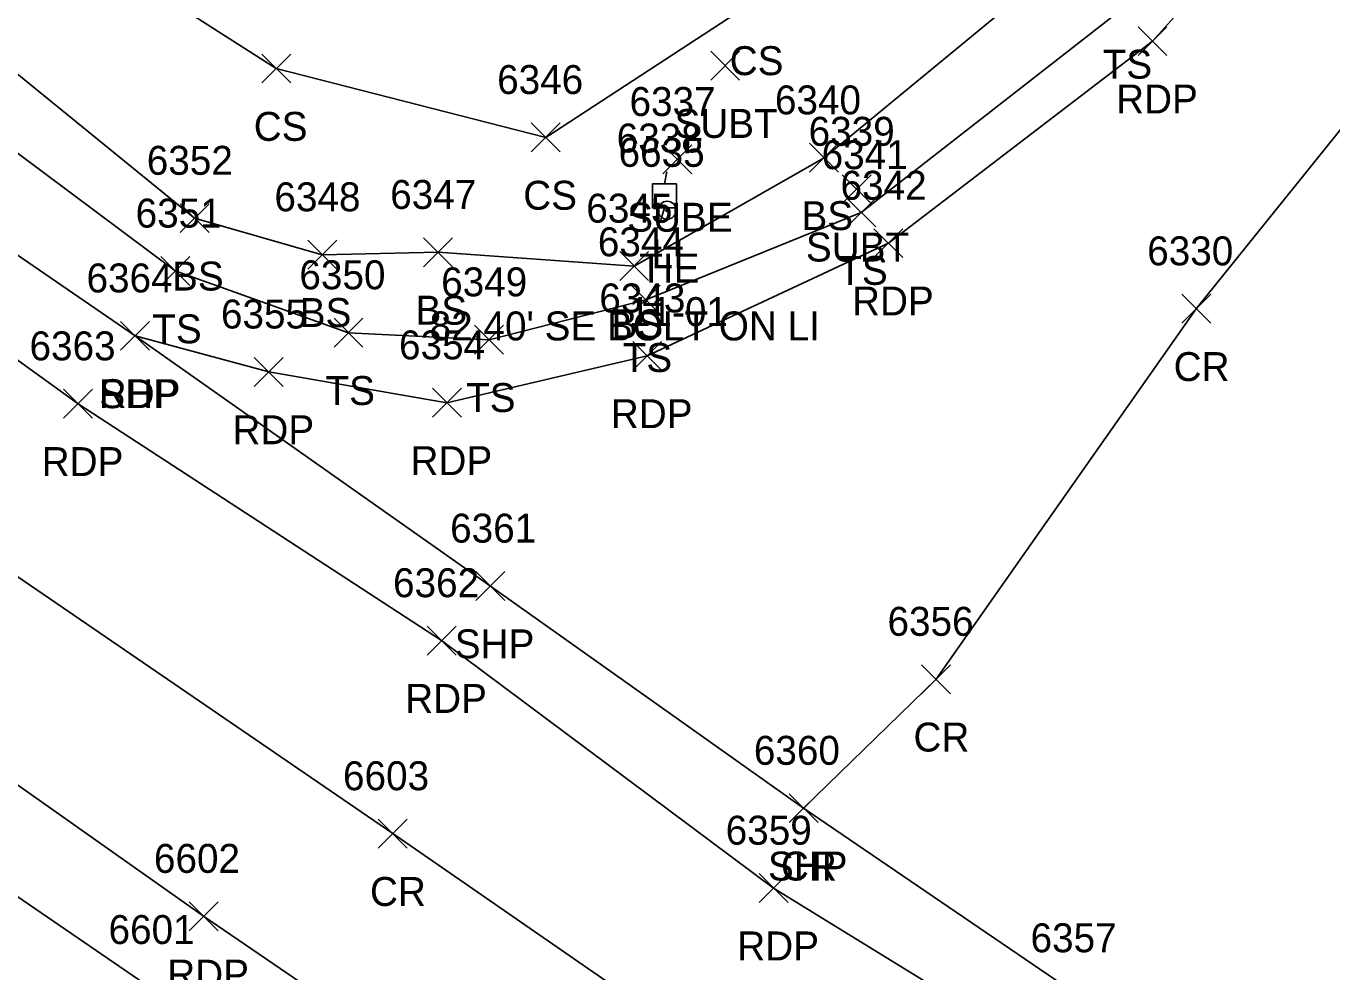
# Model space of a CAD drawing. Extents: x 1505656 to 1508446, y 700805 to 703031.
# Drawn here: x 1507831.5 to 1507921.8, y 701178.2 to 701243.5 of the extents above; entities that cross this region are included whole.
import ezdxf

# ---------------------------------------------------------------- set-up
doc = ezdxf.new("R2010")
doc.units = 0
for name, color, linetype in [('C_A', 7, 'Continuous'), ('C_C', 7, 'Continuous'), ('C_I', 7, 'Continuous'), ('CBP', 7, 'Continuous'), ('L_A', 7, 'Continuous'), ('L_I', 7, 'Continuous'), ('L_TIC', 7, 'Continuous'), ('LELB', 7, 'Continuous'), ('P_A', 7, 'Continuous'), ('P_I', 7, 'Continuous'), ('P_TIC', 7, 'Continuous'), ('PET', 7, 'Continuous'), ('PRC', 7, 'Continuous'), ('PSP', 7, 'Continuous'), ('U_A', 7, 'Continuous'), ('U_C', 7, 'Continuous'), ('U_I', 7, 'Continuous'), ('U_TIC', 7, 'Continuous'), ('ULP', 7, 'Continuous')]:
    doc.layers.add(name, color=color, linetype=linetype)

msp = doc.modelspace()

# ---------------------------------------------------------------- linework, layer by layer
at = {"layer": 'CBP'}
for radius in [0.625, 0.0833]:
    msp.add_circle((1507875.831, 701230.817), radius, dxfattribs=at)
at = {"layer": 'L_TIC'}
for points in [[(1507847.824, 701239.613), (1507849.824, 701241.613)], [(1507849.824, 701239.613), (1507847.824, 701241.613)], [(1507866.449, 701234.851), (1507868.449, 701236.851)], [(1507868.449, 701234.851), (1507866.449, 701236.851)], [(1507885.679, 701233.442), (1507887.679, 701235.442)], [(1507887.679, 701233.442), (1507885.679, 701235.442)], [(1507842.178, 701229.266), (1507844.178, 701231.266)], [(1507844.178, 701229.266), (1507842.178, 701231.266)], [(1507888.255, 701229.657), (1507890.255, 701231.657)], [(1507890.255, 701229.657), (1507888.255, 701231.657)], [(1507851, 701226.743), (1507853, 701228.743)], [(1507853, 701226.743), (1507851, 701228.743)], [(1507859.004, 701226.906), (1507861.004, 701228.906)], [(1507861.004, 701226.906), (1507859.004, 701228.906)], [(1507840.841, 701225.616), (1507842.841, 701227.616)], [(1507842.841, 701225.616), (1507840.841, 701227.616)], [(1507872.557, 701225.957), (1507874.557, 701227.957)], [(1507874.557, 701225.957), (1507872.557, 701227.957)], [(1507873.353, 701223.633), (1507875.353, 701225.633)], [(1507875.353, 701223.633), (1507873.353, 701225.633)], [(1507852.813, 701221.352), (1507854.813, 701223.352)], [(1507854.813, 701221.352), (1507852.813, 701223.352)], [(1507862.532, 701220.863), (1507864.532, 701222.863)], [(1507864.532, 701220.863), (1507862.532, 701222.863)]]:
    msp.add_lwpolyline(points, dxfattribs=at)
at = {"layer": 'LELB'}
for points in [[(1508013.247, 701346.104), (1507984.495, 701324.829), (1507956.473, 701302.426), (1507918.756, 701270.827), (1507904.064, 701248.775), (1507886.679, 701234.442), (1507873.557, 701226.957), (1507860.004, 701227.906), (1507852, 701227.743), (1507843.178, 701230.266), (1507815.133, 701253.103), (1507771.903, 701280.143), (1507738.232, 701303.159), (1507696.593, 701329.666), (1507663.203, 701353.106), (1507646.455, 701366.454)], [(1508015.052, 701343.612), (1507986.327, 701322.014), (1507960.585, 701298.459), (1507925.277, 701262.854), (1507907.529, 701244.915), (1507889.255, 701230.657), (1507874.353, 701224.633), (1507863.532, 701221.863), (1507853.813, 701222.352), (1507841.841, 701226.616), (1507812.686, 701248.413), (1507769.981, 701276.582), (1507735.611, 701299.665), (1507693.172, 701327.017), (1507661.005, 701349.446), (1507641.822, 701365.101)], [(1507916.993, 701276.137), (1507899.543, 701258.765), (1507881.721, 701245.155), (1507867.449, 701235.851), (1507848.824, 701240.613), (1507819.444, 701259.37), (1507776.79, 701286.758), (1507743.58, 701313.789), (1507698.164, 701337.222), (1507663.203, 701353.106)]]:
    msp.add_lwpolyline(points, dxfattribs=at)
at = {"layer": 'P_TIC'}
for points in [[(1507908.38, 701241.504), (1507910.38, 701243.504)], [(1507910.38, 701241.504), (1507908.38, 701243.504)], [(1507890.129, 701227.541), (1507892.129, 701229.541)], [(1507892.129, 701227.541), (1507890.129, 701229.541)], [(1507911.409, 701223.006), (1507913.409, 701225.006)], [(1507913.409, 701223.006), (1507911.409, 701225.006)], [(1507838.062, 701221.133), (1507840.062, 701223.133)], [(1507840.062, 701221.133), (1507838.062, 701223.133)], [(1507838.062, 701221.133), (1507840.062, 701223.133)], [(1507840.062, 701221.133), (1507838.062, 701223.133)], [(1507873.456, 701219.751), (1507875.456, 701221.751)], [(1507875.456, 701219.751), (1507873.456, 701221.751)], [(1507847.305, 701218.64), (1507849.305, 701220.64)], [(1507849.305, 701218.64), (1507847.305, 701220.64)], [(1507834.121, 701216.44), (1507836.121, 701218.44)], [(1507836.121, 701216.44), (1507834.121, 701218.44)], [(1507859.612, 701216.505), (1507861.612, 701218.505)], [(1507861.612, 701216.505), (1507859.612, 701218.505)], [(1507862.625, 701203.839), (1507864.625, 701205.839)], [(1507864.625, 701203.839), (1507862.625, 701205.839)], [(1507859.245, 701200.065), (1507861.245, 701202.065)], [(1507861.245, 701200.065), (1507859.245, 701202.065)], [(1507893.427, 701197.396), (1507895.427, 701199.396)], [(1507895.427, 701197.396), (1507893.427, 701199.396)], [(1507884.269, 701188.479), (1507886.269, 701190.479)], [(1507886.269, 701188.479), (1507884.269, 701190.479)], [(1507884.269, 701188.479), (1507886.269, 701190.479)], [(1507886.269, 701188.479), (1507884.269, 701190.479)], [(1507855.866, 701186.721), (1507857.866, 701188.721)], [(1507857.866, 701186.721), (1507855.866, 701188.721)], [(1507882.198, 701182.957), (1507884.198, 701184.957)], [(1507884.198, 701182.957), (1507882.198, 701184.957)], [(1507842.799, 701181.008), (1507844.799, 701183.008)], [(1507844.799, 701181.008), (1507842.799, 701183.008)]]:
    msp.add_lwpolyline(points, dxfattribs=at)
at = {"layer": 'PET'}
for points in [[(1508016.501, 701342.291), (1507987.691, 701321.256), (1507962.249, 701296.772), (1507926.14, 701261.093), (1507909.38, 701242.504), (1507891.129, 701228.541), (1507874.456, 701220.751), (1507860.612, 701217.505), (1507848.305, 701219.64), (1507839.062, 701222.133)], [(1508337.307, 700875.804), (1508299.118, 700901.217), (1508243.207, 700939.461), (1508171.951, 700987.77), (1508130.481, 701015.517), (1508098.002, 701037.641), (1508055.469, 701066.532), (1508022.234, 701089.23), (1507988.571, 701112.227), (1507963.258, 701129.325), (1507945.797, 701141.835), (1507902.274, 701172.194), (1507883.198, 701183.957), (1507860.245, 701201.065), (1507835.121, 701217.44), (1507805.58, 701238.78), (1507763.248, 701266.991), (1507728.858, 701291.359), (1507688.432, 701318.434), (1507655.643, 701340.89)], [(1508325.469, 700853.929), (1508286.341, 700880.084), (1508228.39, 700919.425), (1508193.529, 700942.688), (1508162.03, 700964.202), (1508126.361, 700988.762), (1508069.255, 701027.686), (1508039.882, 701046.838), (1507982.914, 701086.278), (1507949.883, 701109.29), (1507927.437, 701124.576), (1507885.021, 701153.862), (1507843.799, 701182.008), (1507811.491, 701204.798), (1507770.513, 701232.431), (1507732.443, 701258.918), (1507681.2, 701293.35)]]:
    msp.add_lwpolyline(points, dxfattribs=at)
at = {"layer": 'PRC'}
for points in [[(1508022.549, 701332.623), (1507994.761, 701311.423), (1507970.363, 701289.405), (1507934.615, 701251.602), (1507912.409, 701224.006), (1507894.427, 701198.396), (1507885.269, 701189.479)], [(1508330.815, 700865.178), (1508292.577, 700890.762), (1508235.815, 700929.214), (1508200.167, 700952.999), (1508165.621, 700976.67), (1508123.908, 701005.478), (1508090.883, 701028.023), (1508047.996, 701056.518), (1508015.223, 701078.955), (1507981.584, 701102.274), (1507956.812, 701118.999), (1507935.36, 701133.831), (1507892.743, 701162.903), (1507856.866, 701187.721), (1507818.458, 701214.027), (1507776.638, 701243.136), (1507739.634, 701268.403), (1507687.662, 701303.501)]]:
    msp.add_lwpolyline(points, dxfattribs=at)
at = {"layer": 'PSP'}
for points in [[(1508339.198, 700878.522), (1508300.647, 700904.316), (1508290.659, 700911.252), (1508285.71, 700920.134), (1508246.944, 700946.034), (1508214.535, 700968.679), (1508208.308, 700968.429), (1508200.271, 700972.314), (1508174.142, 700990.248), (1508132.472, 701018.549), (1508100.453, 701040.484), (1508057.363, 701069.9), (1508024.073, 701092.522), (1507991.148, 701114.565), (1507965.564, 701132.673), (1507948.13, 701144.998), (1507904.259, 701176.519), (1507885.269, 701189.479), (1507863.625, 701204.839), (1507839.062, 701222.133), (1507808.572, 701243.062), (1507766.968, 701271.373), (1507732.078, 701295.242), (1507690.901, 701323.176)], [(1508322.106, 700849.227), (1508283.293, 700875.615), (1508225.231, 700915.4), (1508190.181, 700938.927), (1508158.852, 700960.019), (1508133.584, 700977.427), (1508108.679, 700994.35), (1508066.548, 701022.65), (1508035.749, 701043.706), (1507979.024, 701080.757), (1507948.088, 701102.185), (1507924.338, 701119.432), (1507882.156, 701148.697), (1507840.095, 701177.09), (1507807.521, 701199.386), (1507768.584, 701225.936), (1507728.955, 701254.657), (1507678.676, 701288.489)]]:
    msp.add_lwpolyline(points, dxfattribs=at)
at = {"layer": 'U_TIC'}
for points in [[(1507878.847, 701239.813), (1507880.847, 701241.813)], [(1507880.847, 701239.813), (1507878.847, 701241.813)], [(1507875.542, 701233.331), (1507877.542, 701235.331)], [(1507877.542, 701233.331), (1507875.542, 701235.331)], [(1507887.931, 701231.271), (1507889.931, 701233.271)], [(1507889.931, 701231.271), (1507887.931, 701233.271)]]:
    msp.add_lwpolyline(points, dxfattribs=at)
at = {"layer": 'ULP'}
for p, q in [((1507875.821, 701233.475), (1507875.655, 701232.642)), ((1507874.821, 701230.975), (1507874.821, 701232.642)), ((1507874.821, 701232.642), (1507876.488, 701232.642)), ((1507875.655, 701231.808), (1507875.655, 701231.808)), ((1507876.488, 701232.642), (1507876.488, 701230.975)), ((1507876.488, 701230.975), (1507874.821, 701230.975)), ((1507875.405, 701230.142), (1507875.655, 701230.975))]:
    msp.add_line(p, q, dxfattribs=at)

# ---------------------------------------------------------------- texts
at = {"layer": 'C_A'}
msp.add_text('TIE', height=2, dxfattribs=at).set_placement((1507873.91, 701225.817))
at = {"layer": 'C_C'}
msp.add_text("82.40' SE BOLT ON LI", height=2, dxfattribs=at).set_placement((1507859.422, 701221.817))
at = {"layer": 'C_I'}
msp.add_text('6635', height=2, dxfattribs=at).set_placement((1507872.477, 701233.817))
at = {"layer": 'L_A'}
for s, p in [('CS', (1507880.162, 701240.155)), ('TS', (1507905.938, 701239.915)), ('CS', (1507847.265, 701235.613)), ('CS', (1507865.89, 701230.851)), ('BS', (1507885.12, 701229.442)), ('BS', (1507841.619, 701225.266)), ('TS', (1507887.664, 701225.657)), ('BS', (1507850.441, 701222.743)), ('BS', (1507858.444, 701222.906)), ('BS', (1507871.998, 701221.957)), ('TS', (1507840.251, 701221.616)), ('TS', (1507872.763, 701219.633)), ('TS', (1507852.222, 701217.352)), ('TS', (1507861.941, 701216.863))]:
    msp.add_text(s, height=2, dxfattribs=at).set_placement(p)
at = {"layer": 'L_I'}
for s, p in [('6346', (1507864.087, 701238.851)), ('6340', (1507883.285, 701237.442)), ('6341', (1507886.515, 701233.657)), ('6352', (1507839.871, 701233.266)), ('6348', (1507848.693, 701230.743)), ('6347', (1507856.696, 701230.906)), ('6345', (1507870.25, 701229.957)), ('6351', (1507839.101, 701229.616)), ('6344', (1507871.046, 701227.633)), ('6350', (1507850.419, 701225.352)), ('6349', (1507860.217, 701224.863))]:
    msp.add_text(s, height=2, dxfattribs=at).set_placement(p)
at = {"layer": 'P_A'}
for s, p in [('RDP', (1507906.868, 701237.504)), ('RDP', (1507888.617, 701223.541)), ('CR', (1507910.842, 701219.006)), ('SHP', (1507836.597, 701217.133)), ('RDP', (1507836.55, 701217.133)), ('RDP', (1507871.944, 701215.751)), ('RDP', (1507845.793, 701214.64)), ('RDP', (1507832.609, 701212.44)), ('RDP', (1507858.1, 701212.505)), ('SHP', (1507861.16, 701199.839)), ('RDP', (1507857.733, 701196.065)), ('CR', (1507892.86, 701193.396)), ('SHP', (1507882.805, 701184.479)), ('CR', (1507883.702, 701184.479)), ('CR', (1507855.299, 701182.721)), ('RDP', (1507880.686, 701178.957)), ('RDP', (1507841.288, 701177.008))]:
    msp.add_text(s, height=2, dxfattribs=at).set_placement(p)
at = {"layer": 'P_I'}
for s, p in [('6342', (1507887.822, 701231.541)), ('6330', (1507909.015, 701227.006)), ('6364', (1507835.707, 701225.133)), ('6364', (1507835.707, 701225.133)), ('6343', (1507871.148, 701223.751)), ('6355', (1507844.998, 701222.64)), ('6363', (1507831.767, 701220.44)), ('6354', (1507857.305, 701220.505)), ('6361', (1507860.837, 701207.839)), ('6362', (1507856.891, 701204.065)), ('6356', (1507891.065, 701201.396)), ('6360', (1507881.828, 701192.479)), ('6360', (1507881.828, 701192.479)), ('6603', (1507853.433, 701190.721)), ('6359', (1507879.883, 701186.957)), ('6602', (1507840.366, 701185.008)), ('6601', (1507837.229, 701180.09)), ('6357', (1507900.952, 701179.519))]:
    msp.add_text(s, height=2, dxfattribs=at).set_placement(p)
at = {"layer": 'U_A'}
for s, p in [('SUBT', (1507876.343, 701235.813)), ('SUBE', (1507873.078, 701229.331)), ('SUBT', (1507885.428, 701227.271)), ('LI', (1507874.757, 701226.808))]:
    msp.add_text(s, height=2, dxfattribs=at).set_placement(p)
at = {"layer": 'U_C'}
msp.add_text('11-01', height=2, dxfattribs=at).set_placement((1507873.198, 701222.808))
at = {"layer": 'U_I'}
for s, p in [('6337', (1507873.235, 701237.331)), ('6339', (1507885.616, 701235.271)), ('6338', (1507872.348, 701234.808))]:
    msp.add_text(s, height=2, dxfattribs=at).set_placement(p)

doc.saveas('drawing.dxf')
